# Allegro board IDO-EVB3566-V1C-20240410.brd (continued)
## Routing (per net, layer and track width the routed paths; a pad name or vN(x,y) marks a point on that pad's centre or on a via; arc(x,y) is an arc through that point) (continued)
PMIC_32KHZ_OUT_WIFI: length 48.7
  TOP w0.127: R74.1 84.74,32.7 v1(84.94,32.89) ; M1.180 48.53,47.61 49.33,46.81 49.33,39.09 v1(50.38,38.04)
  BOTTOM w0.127: v1(50.38,38.04) 50.62,37.8 64.43,37.8 64.79,37.45 70.08,37.45 73.36,34.16 81.81,34.16 83.08,32.89 v1(84.94,32.89)
PMIC_EXT_EN: length 83.2
  TOP w0.127: v1(72.37,44.4) 73.04,45.06 M1.167 ; v1(26.62,28.07) 25.9,28.07 25.5,27.67 25.5,25.68 v1(25.78,25.4) ; v1(13.38,21.89) 13.04,22.23 12.63,22.23 R11.1 ; v1(51.69,45.72) 51.33,45.36 51.33,34.48 50.83,33.99 v1(50.27,33.99)
  BOTTOM w0.127: v1(13.38,21.89) 16.7,21.89 18,23.18 18,24.89 18.25,25.15 25.53,25.15 v1(25.78,25.4) ; v1(51.69,45.72) 52.2,46.23 53.09,46.23 53.47,45.85 59.05,45.85 59.41,45.49 67.08,45.49 67.69,46.1 68.76,46.1 70.25,44.61 72.16,44.61 v1(72.37,44.4) ; v1(26.62,28.07) 26.79,28.07 27.87,29.15 28.26,29.15 28.68,28.73 30.24,28.73 30.97,29.46 31.99,29.46 31.99,29.46 32.13,29.46 35.47,32.81 48.58,32.81 49.26,33.49 49.38,33.49 49.88,33.99 v1(50.27,33.99)
PMIC_PWRON: length 89.2
  TOP w0.127: v1(67.89,45.47) 67.9,45.48 67.9,46.28 69.04,47.42 71.42,47.42 72.78,46.06 M1.168 ; v1(52,34.54) 51.79,34.76 51.79,45.15 v1(52.37,45.73) ; J46.2 9.3,32.1 8.89,32.51 v1(5.97,32.51)
  BOTTOM w0.127: v1(5.97,32.51) 6.54,31.94 D82.10 D82.1 7.94,31.94 8.09,31.78 10.13,31.78 11.14,30.77 12.61,30.77 13.69,31.85 16.23,31.85 16.41,32.03 21.27,32.03 22.35,30.95 26.96,30.95 27.71,31.7 30.43,31.7 30.66,31.93 31.77,31.93 34.51,34.67 46.3,34.67 47.06,35.43 51.11,35.43 v1(52,34.54) ; v1(67.89,45.47) 67.89,45.46 67.6,45.16 59.27,45.16 58.92,45.52 52.58,45.52 v1(52.37,45.73)
PMIC_VDC: length 8
  TOP w0.381: M1.169 72.6,47.06 71.91,47.76 v1(71.91,47.88)
  BOTTOM w0.127: D86.C 76.47,47.85 75.55,47.85 R20.2 R18.1 73.4,47.8 71.98,47.8 v1(71.91,47.88)
PWM0_M0_EDP: length 76.3
  TOP w0.127: v1(24.23,10.57) 24.07,10.41 J5.8 ; v1(64.01,17.44) 63.91,17.54 63.91,34.55 67.63,38.27 71.29,38.27 73.08,40.06 M1.162
  BOTTOM w0.127: v1(24.23,10.57) 24.48,10.82 34.88,10.82 35.39,10.3 38.95,10.3 45.15,16.51 46.03,16.51 47.17,17.65 63.8,17.65 v1(64.01,17.44)
PWM4_LVDS: length 42.4
  TOP w0.127: M1.155 73.07,33.06 72.54,32.54 72.54,31.93 71.47,30.86 69.52,30.86 69.09,30.43 69.09,29.45 68.31,28.67 66.01,28.67 65.25,27.91 65.25,18.29 65.49,18.05 65.49,17.48 66.03,16.94 66.03,15.91 66.52,15.42 66.52,15.06 66.53,15.05 66.53,14.71 66.52,14.7 66.52,13.79 66.72,13.59 68.23,13.59 68.38,13.74 68.92,13.74 69.2,13.46 70.62,13.46 71.38,12.71 71.5,12.63 71.62,12.58 71.76,12.55 71.9,12.55 72.03,12.57 74.47,12.57 74.78,12.88 75.41,12.88 75.7,12.59 75.7,11.02 74.8,10.12 74.8,7.5 75.05,7.25 J7.35
PWM5_MIPI: length 58.8
  TOP w0.127: v1(69.32,15.19) 69.32,15.72 68.89,16.15 68.89,16.7 68.78,16.81 68.78,18.8 67.97,19.61 66.5,19.61 66.29,19.81 66.29,27.36 66.59,27.66 68.8,27.66 69.47,28.32 72.25,28.32 72.51,28.06 M1.150 ; v1(49.73,14.13) 49.47,13.87 49.47,13.78 48.94,13.25 v1(48.94,12.87)
  BOTTOM w0.127: U6.4 44.67,4.76 45.11,4.32 R49.2 45.4,4.32 45.4,4.7 44.96,5.14 44.96,7.62 45.33,7.99 45.68,7.99 46.35,8.66 46.35,10.29 46.74,10.67 47.12,10.67 47.62,10.16 48.26,10.16 48.66,10.56 48.66,12.59 v1(48.94,12.87) ; v1(69.32,15.19) 69.14,15.37 68.53,15.37 67.61,16.28 66.78,16.28 65.95,15.45 63.18,15.45 62.76,15.87 51.26,15.87 49.73,14.35 v1(49.73,14.13)
PWM6_OUT: length 99.2
  TOP w0.127: J31.4 8,17.34 8,15.24 8.2,15.04 10.21,15.04 10.41,15.23 D45.2 D45.9 12.93,15.23 v1(13.47,14.7) ; v1(72.26,14.96) 72.54,15.24 72.54,21.92 71.68,22.79 71.68,24.56 73.18,26.06 M1.148
  BOTTOM w0.127: v1(13.47,14.7) 11.8,14.7 10.16,13.06 10.16,9.14 12.19,7.11 17.91,7.11 18.41,6.6 23.1,6.6 23.59,7.09 28.29,7.09 28.7,7.49 32.26,7.49 32.66,7.09 36.19,7.09 36.74,7.64 39.87,7.64 45.86,13.62 46.37,13.62 46.94,14.19 49.12,14.19 51.05,16.13 62.87,16.13 63.29,15.71 65.85,15.71 66.68,16.54 67.74,16.54 68.43,15.85 69.09,15.85 70,16.76 70.7,16.76 71.01,16.45 71.01,16.03 72.09,14.96 v1(72.26,14.96)
PWM7_IR: length 104.4
  TOP w0.127: v1(68.43,16.51) 68.43,16.51 68.5,16.59 68.5,18.54 67.69,19.35 66.37,19.35 66.04,19.68 66.04,27.47 66.48,27.91 68.63,27.91 69.29,28.57 71.25,28.57 71.73,29.06 M1.151 ; v1(13.46,15.37) 13.1,15.73 D45.10 D45.1 10.27,15.73 9.91,15.37 8.38,15.37 8.26,15.49 8.26,19.08 J31.2
  BOTTOM w0.127: v1(13.46,15.37) 13.93,14.91 13.93,14.47 13.21,13.74 11.42,13.74 10.41,12.74 10.41,9.25 11.49,8.17 17.87,8.17 19.18,6.86 23,6.86 23.48,7.34 28.19,7.34 28.59,7.75 32.37,7.75 32.77,7.34 36.09,7.34 36.76,8.02 39.9,8.02 45.76,13.88 46.27,13.88 46.84,14.45 49,14.45 50.93,16.38 62.97,16.38 63.39,15.96 64.73,15.96 64.77,16 65.79,16 66.57,16.79 68.16,16.79 68.43,16.52 v1(68.43,16.51)
RECOVERY_KEY: length 5.8
  BOTTOM w0.127: R25.2 62.36,64.84 C33.2 61.31,64.87 D5.1 60.2,65.63 61.16,66.6 SW4.3
RESETN: length 102.4
  TOP w0.127: v1(81.14,46.98) 80.97,46.81 80.31,46.81 80.09,47.03 80.09,47.61 79.82,47.88 79.44,47.88 78.94,47.38 77.99,47.38 77.74,47.13 77.74,46.19 77.46,45.92 v1(77.46,44.24) ; v1(50.64,34.92) 50.9,35.18 50.9,45.69 v1(50.96,45.75) ; v1(69.07,45.07) 69.1,45.07 69.54,45.51 M1.222 ; J46.3 9.28,30.85 8.41,31.73 v1(5.84,31.73)
  BOTTOM w0.127: v1(50.64,34.92) 50.52,35.05 47.15,35.05 46.44,34.34 34.72,34.34 31.98,31.6 30.79,31.6 30.56,31.37 27.85,31.37 27.1,30.62 21.58,30.62 20.5,31.7 16.59,31.7 16.26,31.37 13.72,31.37 12.43,30.09 11.1,30.09 9.75,31.44 D82.2 D82.9 6.13,31.44 v1(5.84,31.73) ; v1(50.96,45.75) 51.51,45.19 58.78,45.19 59.13,44.83 68.5,44.83 68.74,45.07 v1(69.07,45.07) 69.07,45.03 69.9,44.2 71.92,44.2 72.18,43.93 77.15,43.93 v1(77.46,44.24) ; v1(81.14,46.98) 81.14,48.4 R1231.2
RMII_CLK_: length 3.5
  BOTTOM w0.127: R1224.2 30.61,18.8 31.47,19.66 32.87,19.66 33.04,19.83 U11.15
RMII_CLK_CTL: length 2
  BOTTOM w0.127: U11.12 34.54,19.94 33.91,19.31 R1214.1
RMII_RST_: length 4.2
  BOTTOM w0.127: R1201.2 R1202.1 C384.2 30.86,23.11 31.12,22.86 U11.21
RN: length 50.7
  TOP w0.102: v1(42.79,21.45) 42.58,21.67 41.96,21.67 41.15,22.48 41.15,38.52 v1(40.94,38.74)
  BOTTOM w0.102: U23.1 30.23,37.64 29.8,37.21 29.08,37.21 28.99,37.11 28.99,36.83 28.73,36.58 27.96,36.58 27.71,36.83 26.42,36.83 26.31,36.73 26.31,35.31 26.34,35.28 26.4,35.28 26.56,35.43 26.56,35.7 26.99,36.13 D81.1 27.9,36.13 28.69,35.34 28.83,35.34 29.69,36.2 30.81,36.2 32.89,38.28 41.05,38.28 41.15,38.38 41.15,38.63 41.05,38.74 v1(40.94,38.74) ; U11.6 36.97,21.86 37.09,21.98 37.45,21.98 38.08,22.61 41.04,22.61 41.98,21.67 42.58,21.67 v1(42.79,21.45)
RP: length 50.7
  TOP w0.102: v1(42.79,22.13) 42.58,21.92 42.07,21.92 41.4,22.58 41.4,38.52 v1(41.61,38.74)
  BOTTOM w0.102: v1(41.61,38.74) 41.4,38.53 41.4,38.28 41.16,38.03 33,38.03 30.91,35.94 29.79,35.94 28.94,35.09 28.5,35.09 27.65,34.23 D81.3 27.11,34.23 26.56,34.79 26.56,34.92 26.45,35.03 26.23,35.03 26.06,35.2 26.06,36.83 26.31,37.08 27.81,37.08 28.07,36.83 28.63,36.83 28.73,36.94 28.73,37.11 28.61,37.24 28.33,37.24 27.69,37.89 U23.3 ; v1(42.79,22.13) 42.58,21.92 42.09,21.92 41.15,22.86 37.97,22.86 37.35,22.23 37.08,22.23 36.95,22.36 U11.5
RXD0: length 2.6
  BOTTOM w0.127: U11.9 36.04,20.03 36.93,19.15 37.18,19.15 R1206.1
RXD1: length 2.8
  BOTTOM w0.127: R1205.1 R1215.1 36.07,19.3 35.54,19.83 U11.10
RXDV: length 2.1
  BOTTOM w0.254: 37.47,20.57 37.18,20.85 U11.8
  BOTTOM w0.381: R1213.1 37.47,20.57
RXN: length 16.2
  TOP w0.102: J12.6 25.91,56.01 25.53,55.63 24.77,55.63 24.55,55.41 24.55,54.81 v1(24.75,54.62)
  BOTTOM w0.102: U23.16 30.23,48.39 29.36,49.25 29.03,49.25 28.96,49.33 28.96,49.64 27.77,50.82 27.77,50.97 28.16,51.36 28.16,51.72 27.73,52.15 27.37,52.15 26.98,51.76 26.83,51.76 26.55,52.05 26.55,52.19 26.94,52.59 26.94,52.94 26.51,53.38 26.15,53.38 25.76,52.98 25.61,52.98 24.59,54 24.59,54.46 v1(24.75,54.62)
RXP: length 16.2
  TOP w0.102: J12.3 22.85,56.01 23.24,55.63 24.03,55.63 24.3,55.36 24.3,54.84 v1(24.07,54.62)
  BOTTOM w0.102: U23.14 27.69,48.64 28.18,49.14 28.56,49.14 28.7,49.28 28.7,49.53 27.51,50.72 27.51,51.07 27.91,51.47 27.91,51.61 27.62,51.9 27.48,51.9 27.08,51.5 26.73,51.5 26.29,51.94 26.29,52.29 26.69,52.69 26.69,52.83 26.4,53.12 26.26,53.12 25.86,52.73 25.51,52.73 24.34,53.9 24.34,54.37 24.09,54.62 v1(24.07,54.62)
S0_RX: length 26.4
  TOP w0.127: v1(16.52,36.3) v1(17.46,36.3)
  BOTTOM w0.127: v1(17.46,36.3) 17.24,36.09 17.24,35.41 16.29,34.46 15.66,34.46 15.42,34.22 U22.13 ; v1(16.52,36.3) 16.52,37.55 13.33,40.74 9.41,40.74 9.25,40.89 R184.2 8.98,41 D43.1 D43.10 6.46,41 6.36,40.9 5.58,40.9 5.08,41.4 5.08,45.21 3.32,46.97 J42.2
S0_TX: length 27.8
  TOP w0.127: v1(16.42,35.6) 16.65,35.83 17.67,35.83 18.13,36.3 v1(18.13,36.32)
  BOTTOM w0.127: v1(16.42,35.6) 16.06,35.96 16.06,37.56 13.16,40.46 9.6,40.46 9.25,40.11 R183.2 8.37,40.5 D43.2 D43.9 6.49,40.5 6.34,40.65 4.82,40.65 4.57,40.89 4.57,43.94 3.54,44.97 J42.3 ; v1(18.13,36.32) 18.13,36.29 17.5,35.66 17.5,35.3 16.4,34.21 16.1,34.21 15.46,33.57 U22.14
S5_RX: length 13
  BOTTOM w0.127: R186.2 9.62,36.82 U22.8 8.52,36.82 8.38,36.96 8.38,39.06 7.94,39.51 D43.4 D43.7 5.98,39.51 5.08,38.61 5.08,38.59 J43.2
S5_TX: length 14.5
  BOTTOM w0.127: J43.3 4.22,35.73 4.22,37.11 6.11,39.01 D43.6 D43.5 7.98,39.01 8.13,38.86 8.13,36.56 8.52,36.17 U22.7 9.84,36.17 R185.2
S7_RX: length 28
  BOTTOM w0.127: U21.13 16.05,27.23 R174.2 17.13,26.16 17.2,26.16 17.75,25.61 17.75,23.33 16.76,22.35 5.46,22.35 1.91,18.8 1.91,15.44 2.38,14.97 J40.2
S7_TX: length 24.9
  BOTTOM w0.127: J40.3 1.65,14.11 1.65,19 3,20.35 5.26,22.61 12.26,22.61 R173.2 13.55,23.89 13.55,24.68 13.08,25.15 13.08,26.29 13.38,26.58 U21.14
S9_RX: length 14.9
  BOTTOM w0.127: R176.2 11.18,25.27 11.02,25.43 11.02,28.47 9.66,29.83 U21.8 8.52,29.83 8,29.31 6.35,29.31 4.57,27.54 4.57,27.18 3.03,25.64 J41.2
S9_TX: length 16.7
  BOTTOM w0.127: J41.3 5.16,26 5.16,27.76 6.35,28.96 8.39,28.96 8.61,29.18 U21.7 9.8,29.18 10.72,28.27 10.72,24.82 10.69,24.79 10.69,23.88 R175.2
SARADC_VIN0/RECOVERY: length 32.3
  TOP w0.127: v1(67.43,50.42) 68.02,50.42 68.93,49.51 68.93,47.85 67.43,46.35 67.43,41.92 67.9,41.44 72.3,41.44 72.92,42.06 M1.164
  BOTTOM w0.127: R25.1 62.38,61.58 64.99,58.97 64.99,56.57 66.48,55.09 66.48,51.37 v1(67.43,50.42)
SARADC_VIN1: length 43.3
  TOP w0.152: M1.231 30.37,39.51 30.43,39.57 31.93,39.57 32.26,39.24 32.26,36.64 31.29,35.67 31.29,31.18 v1(31.24,31.13) ; v1(5.84,30.14) 8.89,30.14 9.43,29.6 J46.4
  BOTTOM w0.152: v1(31.24,31.13) 31.11,31 27.97,31 27.19,30.23 21.33,30.23 20.46,31.1 16.6,31.1 16.5,31 13.85,31 12.51,29.67 11.03,29.67 9.95,30.75 8.26,30.75 7.95,30.44 D82.4 D82.7 6.14,30.44 v1(5.84,30.14)
SARADC_VIN2: length 89
  TOP w0.152: M1.165 71.87,43.06 70.68,44.25 68.99,44.25 v1(68.78,44.46) ; v1(5.84,29.47) 8.25,29.47 9.37,28.35 J46.5 ; v1(48.34,46.02) 47.93,45.04 47.93,34.72 v1(47.37,34.16)
  BOTTOM w0.152: v1(48.34,46.02) 49.99,46.02 51.17,44.84 58.64,44.84 58.99,44.49 68.62,44.49 68.65,44.46 v1(68.78,44.46) ; v1(47.37,34.16) 47.21,34 34.86,34 31.51,30.65 28.11,30.65 27.19,29.72 21.34,29.72 20.35,30.7 18,30.7 17.45,30.15 16.59,30.15 16.09,30.65 14,30.65 12.56,29.21 10.99,29.21 9.93,30.26 8.28,30.26 7.95,29.94 D82.5 D82.6 6.31,29.94 v1(5.84,29.47)
SDMMC0_CLK_: length 13.4
  BOTTOM w0.127: R160.2 36.58,49.59 C155.2 36.61,49.6 37.03,49.17 39.4,49.17 40.69,50.47 40.69,51.82 40.31,52.2 40.06,52.2 D34.1 D34.10 39.98,53.64 40.06,53.64 40.07,53.64 40.45,53.64 40.46,53.64 41.07,53.64 41.07,53.64 41.22,53.64 41.96,54.38 J21.5
SDMMC0_CLK_SD: length 2.1
  TOP w0.127: M1.37 36.03,50.89 35.69,50.55 v1(35.69,50.32)
  BOTTOM w0.127: v1(35.69,50.32) R160.1
SDMMC0_CMD_SD: length 15.8
  TOP w0.127: M1.33 40.03,50.67 40.16,50.55 41.78,50.55 41.91,50.42 41.91,49.91 41.78,49.78 v1(41.61,49.78)
  BOTTOM w0.127: J21.3 44.16,54.4 44.71,53.84 D33.7 D33.4 44.71,51.73 44.82,51.62 45.35,51.62 45.46,51.51 45.46,51.35 45.35,51.24 44.82,51.24 44.71,51.12 44.71,50.86 44.82,50.75 45.18,50.75 45.29,50.63 45.29,50.48 45.18,50.36 44.82,50.36 44.71,50.25 44.71,49.92 44.42,49.63 43.2,49.63 43.08,49.76 43.08,50.06 42.95,50.19 42.7,50.19 42.57,50.06 42.57,49.76 42.44,49.63 41.77,49.63 v1(41.61,49.78)
SDMMC0_D0_SD: length 12.9
  TOP w0.127: M1.35 v1(38.03,50.42)
  BOTTOM w0.127: J21.7 39.76,54.51 39.23,53.99 D34.9 D34.2 39.23,52.13 39.5,51.87 40.21,51.87 40.36,51.71 40.36,50.55 39.98,50.16 39.25,50.16 39.12,50.29 39.12,51.74 38.99,51.87 38.74,51.87 38.61,51.74 38.61,50.29 38.49,50.16 38.29,50.16 v1(38.03,50.42)
SDMMC0_D1_SD: length 13.4
  TOP w0.127: M1.32 41.03,52.17 40.91,52.3 40.21,52.3 40.08,52.43 40.08,52.68 39.95,52.81 39.7,52.81 39.57,52.68 39.57,52.43 39.45,52.3 39.19,52.3 39.06,52.43 39.06,52.68 38.94,52.81 38.68,52.81 38.56,52.68 38.56,52.43 38.43,52.3 38.18,52.3 38.05,52.43 38.05,52.68 37.92,52.81 37.67,52.81 37.54,52.68 37.54,52.43 37.41,52.3 37.21,52.3 v1(37.01,52.5)
  BOTTOM w0.127: J21.8 38.65,54.83 38.23,54.41 38.23,53.4 D34.7 D34.4 38.24,51.9 37.5,51.17 37.32,51.17 37.01,51.49 v1(37.01,52.5)
SDMMC0_D2_SD: length 17.7
  TOP w0.127: M1.36 37.03,50.72 37.34,50.42 37.34,48.7 v1(37.34,48.7)
  BOTTOM w0.127: v1(37.34,48.7) 42.06,48.7 42.34,48.98 44.66,48.98 46.21,50.53 D33.1 D33.10 46.21,54.09 46.35,54.23 J21.1
SDMMC0_D3_SD: length 13.8
  TOP w0.127: M1.34 39.03,51.23 40.11,50.15 40.61,50.15 40.74,50.02 v1(40.74,49.65)
  BOTTOM w0.127: v1(40.74,49.65) 40.74,49.63 41.07,49.3 44.48,49.3 45.71,50.54 D33.2 D33.9 45.71,54.34 45.25,54.8 J21.2
SDMMC0_DET_L_SD: length 57.7
  TOP w0.127: v1(36.7,50.32) 36.7,49.99 36.88,49.82 36.88,48.9 36.87,48.89 36.87,48.51 36.88,48.5 36.88,44.38 v1(36.84,44.34) ; v1(66.87,45.96) 66.87,41.71 67.52,41.06 M1.163
  BOTTOM w0.127: v1(36.84,44.34) 37.28,44.78 38.82,44.78 39.69,45.65 41.33,45.65 41.7,46.02 43.12,46.02 43.41,45.73 46.03,45.73 46.91,46.61 53.06,46.61 53.57,46.1 59.16,46.1 59.51,45.75 66.71,45.75 66.87,45.91 v1(66.87,45.96) ; J21.9 37.55,54.34 37.74,54.16 D34.6 D34.5 37.17,53.09 36.4,53.09 36.25,52.93 36.25,50.77 v1(36.7,50.32) 36.7,50.29 37.34,49.66 R344.2
SDMMC1_CLK_WIFI: length 66.2
  TOP w0.127: M1.49 24.1,50.06 24.5,49.67 24.5,49.25 25.27,48.47 25.27,47.49 25.92,46.84 27.03,46.84 27.71,46.15 27.71,44.18 28.4,43.48 28.4,41.8 28.88,41.33 32.69,41.33 33.67,40.34 v1(34.64,40.34) ; R67.1 v1(78.29,41.15)
  BOTTOM w0.127: v1(34.64,40.34) 34.64,40.64 36.56,42.57 37.55,42.57 38.24,43.25 39.51,43.25 40.38,44.12 41.63,44.12 41.94,43.81 48.81,43.81 49.81,42.81 52.08,42.81 52.88,42.02 56.01,42.02 56.63,41.4 65.05,41.4 65.78,42.13 67.71,42.13 68.02,42.44 68.76,42.44 69.13,42.08 74.99,42.08 75.92,41.15 v1(78.29,41.15)
SDMMC1_CMD_WIFI: length 70.2
  TOP w0.127: M1.54 24.15,45.06 24.52,44.69 24.52,43.91 25.03,43.4 25.03,41.2 25.66,40.56 27.46,40.56 28.02,40.01 28.02,38.64 29.07,37.59 30.08,37.59 30.42,37.94 31.27,37.94 31.29,37.91 v1(31.52,37.91) ; v1(79.88,41.89) 79.88,42.04 79.19,42.73 R66.2 79.55,42.75 79.76,42.55 79.88,42.55 80.51,41.92 U10.16
  BOTTOM w0.127: v1(79.88,41.89) 79.63,42.14 75.88,42.14 75.44,42.59 69.34,42.59 68.95,42.98 67.83,42.98 67.5,42.64 65.57,42.64 65.26,42.33 56.42,42.33 56.22,42.53 53.7,42.53 52.91,43.32 50.02,43.32 49.02,44.32 42.15,44.32 41.84,44.63 40.17,44.63 39.3,43.76 38,43.76 37.33,43.1 36.37,43.1 32.64,39.37 32.64,38.73 31.82,37.91 v1(31.52,37.91)
SDMMC1_D0_WIFI: length 69.7
  TOP w0.127: v1(33.27,39.16) 33.27,39.75 32.32,40.71 28.49,40.71 27.64,41.56 27.64,43.23 27.28,43.59 26.14,43.59 25.29,44.44 25.29,45.4 25.02,45.67 25.02,46.66 24.51,47.17 24.51,47.62 24.07,48.06 M1.51 ; U10.18 80.45,40.12 80.26,40.31 80.13,40.31 v1(79.88,40.56) 79.66,40.33 79.66,40.16 79.19,39.69 R65.2
  BOTTOM w0.127: v1(33.27,39.16) 33.27,39.33 33.57,39.62 34.93,39.62 35.48,40.17 35.48,40.77 36.77,42.06 37.76,42.06 38.45,42.75 39.72,42.75 40.59,43.61 41.42,43.61 41.8,43.24 48.67,43.24 50.4,41.51 55.8,41.51 56.42,40.89 65.48,40.89 66.1,41.51 74.63,41.51 75.88,40.26 79.59,40.26 v1(79.88,40.56)
SDMMC1_D1_WIFI: length 68.8
  TOP w0.127: U10.19 80.21,39.22 79.89,39.54 v1(79.89,39.73) ; M1.50 23.96,49.06 24.77,48.26 24.77,47.28 25.54,46.5 25.54,44.54 26.24,43.84 27.38,43.84 28.02,43.21 28.02,41.58 28.64,40.96 32.42,40.96 33.95,39.43 v1(33.95,39.16)
  BOTTOM w0.127: v1(33.95,39.16) 34.83,39.16 35.74,40.07 35.74,40.66 36.88,41.8 37.87,41.8 38.55,42.49 39.83,42.49 40.69,43.36 41.32,43.36 41.69,42.99 48.56,42.99 50.29,41.26 55.7,41.26 56.32,40.64 65.58,40.64 66.2,41.26 74.52,41.26 76.05,39.73 v1(79.89,39.73)
SDMMC1_D2_WIFI: length 68.5
  TOP w0.127: v1(31.01,37.47) 30.61,37.47 30.48,37.34 28.96,37.34 27.83,38.47 25.85,38.47 25.39,38.93 25.39,40.48 24.78,41.09 24.78,43.29 24.01,44.06 M1.55 ; v1(79.51,43.44) 79.88,43.81 80.24,43.81 80.34,43.72 U10.14
  BOTTOM w0.127: v1(79.51,43.44) 79.15,43.09 69.55,43.09 69.16,43.48 67.62,43.48 67.29,43.15 65.36,43.15 65.05,42.84 56.63,42.84 56.44,43.03 53.91,43.03 53.12,43.83 50.23,43.83 49.23,44.83 42.36,44.83 42.05,45.14 39.96,45.14 39.09,44.27 37.79,44.27 37.12,43.6 35.98,43.6 34.03,41.65 33.61,41.65 33.27,41.31 33.27,40.39 32.38,39.5 32.38,38.99 31.77,38.38 31.28,38.38 31.01,38.1 v1(31.01,37.47)
SDMMC1_D3_WIFI: length 69.4
  TOP w0.127: U10.15 80.56,42.82 80.39,42.99 v1(80.01,42.99) ; v1(33.74,41.12) 33.11,41.75 30.89,41.75 30.73,41.91 30.73,42.34 30.76,42.37 31,42.37 31.12,42.48 31.12,42.64 31,42.75 30.73,42.75 30.71,42.78 30.71,43.27 30.47,43.51 28.91,43.51 27.99,44.42 27.99,47.33 27.97,47.36 27.67,47.36 27.56,47.47 27.56,47.63 27.67,47.74 28.02,47.74 28.13,47.85 28.13,48.01 28.02,48.12 27.67,48.12 27.56,48.23 27.56,48.39 27.67,48.5 28.02,48.5 28.13,48.61 28.13,48.95 26.9,50.19 26.01,50.19 25.03,51.17 M1.48
  BOTTOM w0.127: v1(33.74,41.12) 33.86,41.12 36.09,43.35 37.23,43.35 37.89,44.02 39.19,44.02 40.06,44.88 41.95,44.88 42.25,44.58 49.13,44.58 50.13,43.58 53.01,43.58 53.81,42.78 56.33,42.78 56.52,42.59 65.15,42.59 65.46,42.9 67.39,42.9 67.73,43.23 69.05,43.23 69.44,42.84 79.86,42.84 v1(80.01,42.99)
SPI3_CLK_M1_OUT: length 65.8
  TOP w0.127: M1.206 52.48,14.84 51.18,16.14 v1(48.48,16.14) ; J31.1 10.43,18.91 D44.1 D44.10 13.06,18.91 v1(13.34,19.18)
  BOTTOM w0.127: v1(13.34,19.18) 13.06,18.91 12.68,18.91 12.45,18.67 12.45,16.38 12.83,16 13.55,16 14.44,15.12 14.44,14.26 13.42,13.23 11.63,13.23 10.92,12.53 10.92,9.46 11.62,8.76 20.11,8.76 20.76,9.41 23.17,9.41 23.46,9.12 27.28,9.12 28.22,10.06 34.56,10.06 35.08,9.54 39.26,9.54 45.12,15.4 45.64,15.4 47,16.76 47.85,16.76 v1(48.48,16.14)
SPI3_CS0_M1_OUT: length 31.7
  TOP w0.127: v1(13.44,16.98) 13.2,16.98 13.13,16.91 D44.6 D44.5 10.68,16.91 v1(10.29,16.51) ; v1(35.79,15.77) 35.73,15.77 35.58,15.62 M1.201
  BOTTOM w0.127: v1(10.29,16.51) 10.29,15.34 J31.7 ; v1(35.79,15.77) 35.58,15.77 35.38,15.57 35.08,15.57 35.08,15.57 34.35,15.57 33.06,16.86 27.63,16.86 26.8,17.7 21.7,17.7 20.98,18.41 18.54,18.41 17.02,16.89 15.38,16.89 15.3,16.98 v1(13.44,16.98)
SPI3_MISO_M1_OUT: length 34
  TOP w0.127: M1.202 38.58,16.03 v1(37.86,16.75) ; v1(13.42,17.65) 13.19,17.65 12.94,17.41 D44.7 D44.4 10.36,17.41 J31.5
  BOTTOM w0.127: v1(37.86,16.75) 37.85,16.75 37.32,16.23 35.38,16.23 34.98,15.82 34.46,15.82 33.16,17.12 27.73,17.12 26.9,17.95 21.8,17.95 21.08,18.67 18.42,18.67 17.12,17.37 15.57,17.37 15.29,17.65 v1(13.42,17.65)
SPI3_MOSI_M1_OUT: length 55.3
  TOP w0.127: v1(13.38,18.5) 13.28,18.41 D44.9 D44.2 9.36,18.41 J31.3 ; M1.204 44.58,15.28 v1(45.21,15.91)
  BOTTOM w0.127: v1(13.38,18.5) 12.95,18.08 12.95,16.64 13.08,16.51 13.76,16.51 14.65,15.62 14.95,15.33 14.95,14.05 12.76,11.85 12.13,11.85 11.43,11.15 11.43,9.91 12.06,9.27 18.29,9.27 19.44,10.41 23.27,10.41 23.68,10 26.26,10 26.57,10.31 27.75,10.31 28.01,10.57 34.77,10.57 35.29,10.05 39.05,10.05 42.57,13.56 44.91,15.91 v1(45.21,15.91)
SYS_LED_H: length 86.2
  TOP w0.127: v1(24.77,29) 24.77,29.72 24.42,30.06 M1.69 ; v1(61.1,34.53) 61.09,34.53 61.09,34.54 59.94,35.69 59.94,50.16 60.35,50.57 62.59,50.57 v1(62.74,50.42) ; v1(67.44,65.32) 65.23,63.12 v1(61.85,63.12)
  BOTTOM w0.127: v1(61.85,63.12) 61.85,61.57 64.61,58.81 64.61,54.83 64.14,54.36 64.14,52.32 62.74,50.93 v1(62.74,50.42) ; R1227.1 70.62,62.16 R415.2 67.46,65.32 v1(67.44,65.32) ; v1(24.77,29) 26.95,29 28.26,30.3 31.76,30.3 35.02,33.57 47.44,33.57 48.49,34.62 50.29,34.62 50.45,34.46 50.88,34.46 51.44,33.91 60.45,33.91 61.09,34.54 61.09,34.53 v1(61.1,34.53)
TN: length 56.9
  TOP w0.102: v1(42.4,37.97) 42.61,37.76 42.61,36.75 42.04,36.17 42.04,23.62 42.29,23.37 42.54,23.37 v1(42.75,23.16)
  BOTTOM w0.102: v1(42.75,23.16) 42.54,23.37 37.72,23.37 37.33,22.98 37.08,22.98 36.95,22.86 U11.4 ; U23.6 23.88,37.85 23.11,37.08 22.86,37.08 22.73,36.96 22.73,36.68 22.83,36.58 23.5,36.58 24.08,37.16 25.05,37.16 25.65,36.55 25.65,35.71 25.27,35.33 25.27,34.8 24.7,34.23 D81.4 24.32,34.23 23.5,35.05 22.97,35.05 22.73,34.82 22.73,33.85 22.83,33.75 28.21,33.75 29.9,35.43 31.14,35.43 33.22,37.52 42.48,37.52 42.58,37.62 42.58,37.79 v1(42.4,37.97)
TP: length 56.8
  TOP w0.102: v1(42.75,23.83) 42.54,23.62 42.39,23.62 42.29,23.72 42.29,36.07 42.86,36.64 42.86,37.76 v1(43.07,37.97)
  BOTTOM w0.102: U23.8 21.34,37.48 21.74,37.08 22.23,37.08 22.48,36.83 22.48,36.57 22.73,36.32 23.6,36.32 24.18,36.9 24.94,36.9 25.4,36.45 25.4,35.81 25.34,35.76 25.2,35.76 24.83,36.13 D81.6 24.32,36.13 23.5,35.31 22.86,35.31 22.48,34.92 22.48,33.75 22.73,33.5 28.32,33.5 30,35.18 31.24,35.18 33.32,37.26 42.58,37.26 42.83,37.51 42.83,37.85 42.96,37.97 v1(43.07,37.97) ; v1(42.75,23.83) 42.54,23.62 37.61,23.62 37.23,23.23 37.09,23.23 36.97,23.36 U11.3
TP1_INT: length 35.9
  TOP w0.127: v1(64.26,2) 63.2,3.06 63.2,4.88 63.88,5.56 J9.3 63.88,7.36 64.52,8 v1(65.02,8) ; v1(48.9,4.06) 50.01,5.18 51.66,5.18 52.58,6.1 J8.5
  BOTTOM w0.127: R44.2 67.94,10.46 D18.9 D18.2 67.94,7.74 67.55,7.35 66.1,7.35 65.45,8 v1(65.02,8) ; v1(64.26,2) 63.57,2.69 62.58,2.69 62.16,2.27 49.93,2.27 48.9,3.3 v1(48.9,4.06)
TP1_RST: length 32.2
  TOP w0.127: v1(65.53,7.26) 65.3,7.49 64.52,7.49 64.38,7.35 J9.2 64.38,5.58 63.83,5.03 v1(63.83,4.14) ; J8.4 53.08,6.1 51.9,4.92 50.11,4.92 49.67,4.48 v1(49.67,4.06)
  BOTTOM w0.127: v1(63.83,4.14) 62.64,2.95 62.47,2.95 62.07,2.54 50.01,2.54 49.67,2.89 v1(49.67,4.06) ; R43.2 68.44,9.95 D18.10 D18.1 68.44,7.88 67.66,7.1 65.69,7.1 v1(65.53,7.26)
TP1_SCL: length 37.7
  TOP w0.127: v1(63.58,2.02) 62.79,2.81 62.79,5.03 63.38,5.62 J9.4 63.38,7.88 64.18,8.68 v1(65.02,8.68) ; J8.6 52.08,6.1 51.41,5.43 49.6,5.43 v1(49.39,5.22)
  BOTTOM w0.127: v1(65.02,8.68) 65.13,8.68 66.06,7.75 66.46,7.75 66.94,8.22 D18.4 D18.7 66.94,10.48 R42.1 67.56,11.11 67.56,12.5 R41.2 ; v1(63.58,2.02) 63.16,2.44 62.68,2.44 62.26,2.01 49.65,2.01 48.34,3.32 48.34,4.17 v1(49.39,5.22)
TP1_SDA: length 38.1
  TOP w0.127: v1(62.88,1.97) 62.43,2.42 62.43,5.41 62.88,5.85 J9.5 62.88,7.89 64.14,9.14 v1(65.53,9.14) ; J8.7 51.58,6.09 51.18,5.68 49.12,5.68 v1(48.64,5.21)
  BOTTOM w0.127: v1(62.88,1.97) 62.67,1.76 49.55,1.76 48.09,3.22 48.09,4.65 v1(48.64,5.21) ; R39.2 65.41,12 65.41,11.23 R40.1 66.44,10.2 D18.6 D18.5 66.44,8.16 66.31,8.04 66.13,8.04 66,8.16 66,9.02 65.88,9.14 v1(65.53,9.14)
TXN: length 10.9
  TOP w0.102: J12.2 21.83,56.12 21.46,55.75 21.46,55.6 21.69,55.37 21.69,54.93 v1(21.9,54.72)
  BOTTOM w0.102: U23.11 23.88,48.39 22.61,49.66 22.61,52.55 21.74,53.42 21.74,54.56 v1(21.9,54.72)
TXP: length 10.9
  TOP w0.102: v1(21.23,54.72) 21.44,54.93 21.44,55.27 21.2,55.5 21.2,55.76 20.81,56.15 J12.1
  BOTTOM w0.102: U23.9 21.34,48.64 22.35,49.66 22.35,52.45 21.49,53.31 21.49,54.54 21.31,54.72 v1(21.23,54.72)
UART0_RX: length 80.8
  TOP w0.127: v1(71.66,32.87) 71.76,32.97 71.76,34.19 72.63,35.06 M1.157
  BOTTOM w0.127: v1(71.66,32.87) 71.66,33.3 69.18,35.77 62.91,35.77 62.48,36.2 60.96,36.2 59.94,35.18 53.34,35.18 51.99,36.53 46.61,36.53 45.86,35.77 34.06,35.77 31.33,33.04 30.17,33.04 29.92,32.79 25.6,32.79 25.21,32.4 22.44,32.4 19.52,35.33 19.52,40.81 16.89,43.43 10.16,43.43 9.78,43.05 9.78,41.65 R184.1 R189.1
UART0_TX: length 90
  TOP w0.127: v1(10.74,39.62) 10.74,42.6 v1(10.79,42.65) ; v1(72.08,32.32) 72.08,32.45 72.26,32.64 72.26,33.53 72.8,34.06 M1.156
  BOTTOM w0.127: U22.11 15.68,35.52 15.81,35.65 15.81,37.18 12.85,40.13 10.28,40.13 10.15,40.01 R183.1 v1(10.74,39.62) ; v1(72.08,32.32) 71.94,32.32 71.86,32.4 71.46,32.4 71.19,32.68 71.19,33.4 69.08,35.52 62.8,35.52 62.38,35.94 61.09,35.94 60.07,34.92 53.17,34.92 51.82,36.28 46.72,36.28 45.96,35.52 34.17,35.52 31.44,32.79 30.28,32.79 30.03,32.54 25.7,32.54 25.32,32.15 22.34,32.15 19.21,35.27 19.21,40.76 16.91,43.05 11.2,43.05 v1(10.79,42.65)
UART1_CTSN_M0_WIFI: length 80.6
  TOP w0.127: U10.41 93.04,42.82 93.17,42.7 93.17,41.55 93.5,41.22 93.98,41.22 v1(94.63,40.58) 95.33,41.28 R69.1 ; M1.39 34.03,50.93 35.2,49.76 36.27,49.76 36.63,49.4 36.63,49.01 36.62,49 36.62,48.4 36.63,48.39 36.63,44.79 36.2,44.36 v1(35.94,44.36)
  BOTTOM w0.127: v1(94.63,40.58) 92.66,38.61 86,38.61 79.75,44.86 78.95,44.86 78.89,44.8 72.63,44.8 72.57,44.86 70.35,44.86 68.79,46.42 66.52,46.42 66.09,46 59.62,46 59.2,46.42 53.61,46.42 53.17,46.86 46.81,46.86 45.92,45.98 43.51,45.98 43.22,46.27 41.59,46.27 41.22,45.9 39.58,45.9 38.71,45.03 36.65,45.03 35.98,44.36 v1(35.94,44.36)
UART1_RTSN_M0_WIFI: length 75.6
  TOP w0.127: U10.44 93.06,45.52 94.48,44.1 v1(94.48,42.55) ; v1(34.92,46.66) 34.54,47.04 34.54,50.06 34.03,50.57 33.5,50.57 33.03,51.04 M1.40
  BOTTOM w0.127: v1(34.92,46.66) 36.26,46.66 37.13,45.79 38.4,45.79 39.27,46.66 40.91,46.66 41.28,47.03 43.54,47.03 43.83,46.74 45.46,46.74 46.34,47.62 68.67,47.62 70.67,45.62 72.88,45.62 72.95,45.56 78.39,45.56 78.43,45.59 78.6,45.59 78.64,45.62 80.53,45.62 86.27,39.88 90.42,39.88 93.1,42.55 v1(94.48,42.55)
UART1_RX_M0_WIFI: length 86.3
  TOP w0.127: U10.42 92.91,43.72 93.52,43.1 93.52,42.27 93.75,42.04 v1(93.75,41.78) ; v1(32.78,42.22) 32.12,42.22 30.55,43.79 29.11,43.79 28.24,44.65 28.24,47.4 28.3,47.45 28.3,47.65 28.39,47.75 28.39,48.12 28.39,48.12 28.39,48.51 28.39,48.51 28.39,49.21 27.13,50.47 26.39,50.47 26.03,50.83 M1.47
  BOTTOM w0.127: v1(93.75,41.78) 90.98,39.01 86.06,39.01 79.95,45.12 78.85,45.12 78.81,45.09 78.64,45.09 78.6,45.05 72.74,45.05 72.67,45.12 70.46,45.12 68.9,46.68 68.69,46.68 66.41,46.68 65.99,46.25 59.72,46.25 59.3,46.68 53.71,46.68 53.27,47.12 46.65,47.12 45.77,46.23 43.62,46.23 43.33,46.52 41.49,46.52 41.12,46.15 39.48,46.15 38.61,45.29 33.48,45.29 32.78,44.59 v1(32.78,42.22)
UART1_TX_M0_WIFI: length 86.8
  TOP w0.127: M1.46 27.03,50.97 28.64,49.36 28.64,48.4 28.64,48.4 28.64,48.22 28.64,48.22 28.64,47.64 28.55,47.55 28.55,47.34 28.5,47.29 28.5,44.76 29.21,44.04 30.65,44.04 31.14,43.56 31.44,43.56 v1(32.26,42.74) ; U10.43 93.02,44.62 93.88,43.76 93.88,42.48 v1(94.49,41.88)
  BOTTOM w0.127: v1(94.49,41.88) 94.11,42.25 93.48,42.25 90.6,39.37 86.23,39.37 80.23,45.37 78.74,45.37 78.71,45.34 78.53,45.34 78.5,45.31 72.84,45.31 72.78,45.37 70.56,45.37 69,46.93 68.58,46.93 66.3,46.93 65.88,46.51 59.83,46.51 59.41,46.93 53.82,46.93 53.38,47.37 46.55,47.37 45.66,46.49 43.72,46.49 43.43,46.78 41.38,46.78 41.01,46.41 39.37,46.41 38.5,45.54 33.09,45.54 32.26,44.7 v1(32.26,42.74)
UART2_RX_M0_DEBUG: length 84
  TOP w0.127: R161.1 11.43,50.48 11.43,42.67 v1(11.56,42.55) ; M1.153 72.71,31.06 v1(72.39,30.74)
  BOTTOM w0.127: v1(72.39,30.74) 71.72,30.74 70.61,31.85 70.61,33.62 68.97,35.26 62.7,35.26 62.27,35.69 61.21,35.69 60.2,34.67 53.06,34.67 51.71,36.02 46.83,36.02 46.07,35.26 34.27,35.26 31.52,32.51 30.36,32.51 30.13,32.28 25.81,32.28 25.42,31.9 22.23,31.9 18.96,35.17 18.96,40.65 16.81,42.8 11.68,42.8 11.56,42.67 v1(11.56,42.55)
UART2_TX_M0_DEBUG: length 80.1
  TOP w0.127: v1(10.24,42.04) 10.16,41.95 R162.1 ; M1.152 v1(72.39,30.06)
  BOTTOM w0.127: v1(10.24,42.04) 10.29,42.08 11.85,42.08 12.32,42.55 16.7,42.55 18.7,40.54 18.7,35.06 22.18,31.59 25.47,31.59 25.91,32.03 30.25,32.03 30.48,32.26 31.63,32.26 34.38,35.01 46.17,35.01 46.93,35.77 51.61,35.77 52.96,34.42 60.33,34.42 61.34,35.43 62.17,35.43 62.59,35.01 68.87,35.01 70.33,33.54 70.33,31.78 70.36,31.75 70.36,31.75 71.62,30.48 71.62,30.48 72.05,30.06 v1(72.39,30.06)
UART5_RX_M1: length 46
  TOP w0.127: v1(9.34,37.47) 9.17,37.63 5.5,37.63 4.49,36.62 4.49,21.25 v1(4.78,20.95) ; M1.80 23.1,19.06 v1(22.73,19.43)
  BOTTOM w0.127: v1(4.78,20.95) 4.78,20.99 5.89,22.1 12.51,22.1 13.18,21.42 13.85,21.42 15.8,19.47 22.69,19.47 v1(22.73,19.43) ; R186.1 12.31,38.75 R190.1 9.34,37.53 v1(9.34,37.47)
UART5_TX_M1: length 48.3
  TOP w0.127: v1(5.46,20.94) 4.74,21.66 4.74,36.51 5.61,37.38 8.77,37.38 10.08,36.07 v1(10.54,36.07) ; M1.81 23.09,18.06 v1(22.73,18.42)
  BOTTOM w0.127: v1(22.73,18.42) 22.61,18.42 21.8,19.22 15.7,19.22 13.75,21.17 13.08,21.17 12.4,21.84 6.37,21.84 v1(5.46,20.94) ; U22.10 14.22,36.17 12.8,37.59 12.8,37.59 12.65,37.74 R185.1 10.87,36.31 10.78,36.31 v1(10.54,36.07)
UART7_RX_M2: length 10.6
  TOP w0.127: M1.73 24.03,26.06 v1(24.51,26.54)
  BOTTOM w0.127: v1(24.51,26.54) 23.62,25.65 18.06,25.65 17.39,26.32 R174.1 R178.1
UART7_TX_M2: length 24.5
  TOP w0.127: v1(21.59,26.56) 22.08,27.05 22.08,30.8 22.44,31.16 22.44,36.18 23.32,37.06 M1.62
  BOTTOM w0.127: v1(21.59,26.56) 21.55,26.56 20.29,27.81 18.41,27.81 17.69,28.53 U21.11 14.32,28.53 12.83,27.04 12.83,24.87 13.06,24.64 R173.1
UART9_RX_M2: length 19.8
  TOP w0.127: v1(24.77,27.81) 24.52,28.06 M1.71
  BOTTOM w0.127: v1(24.77,27.81) 22.4,27.81 21.77,28.45 18.63,28.45 18.03,29.04 17.64,29.04 R177.1 16.88,29.8 16.33,29.8 15.83,30.3 14.14,30.3 13.72,29.88 13.72,29.08 12.08,27.45 R176.1
UART9_TX_M2: length 25.5
  TOP w0.127: M1.61 23.46,38.06 22.84,37.45 22.84,36.94 22.18,36.28 22.18,31.26 21.83,30.91 21.83,28.15 v1(21.62,27.94)
  BOTTOM w0.127: v1(21.62,27.94) 21.36,28.19 18.52,28.19 17.93,28.79 16.04,28.79 15.65,29.18 U21.10 14.32,29.18 12.57,27.44 12.57,23.93 R175.1
USB3_HOST1_DM: length 6.6
  TOP w0.114: v1(57.01,56.03) 57.19,55.85 57.53,55.85 57.78,55.59 57.78,54.65 56.65,53.52 56.65,51.94 M1.16
  BOTTOM w0.114: R124.1 56.33,55.92 56.44,55.81 56.79,55.81 v1(57.01,56.03)
USB3_HOST1_DM_2: length 19.3
  TOP w0.114: v1(43.65,60.32) 43.43,60.1 43.43,59.69 44.31,58.82 J16.2
  BOTTOM w0.114: v1(43.65,60.32) 43.38,60.05 43.38,59.35 44.19,58.55 53.12,58.55 53.59,58.08 53.59,56.06 53.85,55.81 54.11,55.81 54.23,55.92 D28.2 54.8,55.72 55.34,55.72 55.43,55.81 R124.2
USB3_HOST1_DP: length 6.7
  TOP w0.114: M1.17 56.41,51.94 56.41,52.36 56.3,52.48 56.22,52.48 56.11,52.59 56.11,52.82 56.22,52.93 56.3,52.93 56.41,53.05 56.41,53.62 57.54,54.75 57.54,55.49 57.43,55.61 57.2,55.61 57.01,55.42 v1(57.01,55.35)
  BOTTOM w0.114: R126.1 56.33,55.45 56.44,55.57 56.79,55.57 v1(57.01,55.35)
USB3_HOST1_DP_2: length 19.3
  TOP w0.114: v1(42.97,60.32) 43.19,60.1 43.19,59.7 42.31,58.82 J16.3
  BOTTOM w0.114: R126.2 55.19,55.48 54.62,55.48 D29.1 54.23,55.45 54.11,55.57 53.75,55.57 53.35,55.96 53.35,57.98 53.02,58.31 44.09,58.31 43.14,59.25 43.14,60.15 v1(42.97,60.32)
USB3_HOST1_SSRXN: length 14
  TOP w0.114: R127.1 52.12,56.41 52.12,56.86 52.32,57.06 52.32,57.4 v1(52.54,57.62) ; M1.14 58.65,51.94 58.65,53.32 58.4,53.57 58.02,53.57 v1(57.8,53.8)
  BOTTOM w0.114: v1(57.8,53.8) 57.58,53.58 53.19,53.58 52.32,54.44 52.32,57.4 v1(52.54,57.62)
USB3_HOST1_SSRXP: length 14.1
  TOP w0.114: v1(57.8,53.12) 58.01,53.33 58.3,53.33 58.41,53.22 58.41,51.94 M1.15 ; R128.1 51.88,56.52 51.88,56.96 52.08,57.16 52.08,57.4 v1(51.86,57.62)
  BOTTOM w0.114: v1(51.86,57.62) 52.08,57.4 52.08,54.34 53.09,53.34 57.58,53.34 v1(57.8,53.12)
USB3_HOST1_SSTXN: length 18.6
  TOP w0.114: v1(59.94,53.59) 60.2,53.34 60.4,53.34 60.65,53.08 60.65,51.94 M1.12 ; v1(50,57.39) 49.78,57.17 49.78,56.46 C125.1
  BOTTOM w0.114: v1(59.94,53.59) 59.69,53.34 58.84,53.34 57.44,51.94 53.17,51.94 49.78,55.33 49.78,57.18 v1(50,57.39)
USB3_HOST1_SSTXP: length 18.5
  TOP w0.114: v1(59.94,52.92) 60.13,53.1 60.3,53.1 60.41,52.98 60.41,51.94 M1.13 ; C126.1 49.54,56.46 49.54,57.17 v1(49.32,57.39)
  BOTTOM w0.114: v1(49.32,57.39) 49.54,57.16 49.54,55.23 53.07,51.7 57.54,51.7 58.94,53.1 59.76,53.1 v1(59.94,52.92)
USB3_HOST1SSRXN: length 19.4
  TOP w0.114: R127.2 52.09,54.81 52.09,53.99 50.56,52.46 44.22,52.46 42.69,54 42.69,54.57 42.56,54.7 D30.1 D30.10 42.56,56.28 42.69,56.41 42.69,56.54 42.58,56.65 41.92,56.65 41.67,56.4 40.4,56.4 40.14,56.66 40.14,57.01 39.31,57.85 J16.5
USB3_HOST1SSRXP: length 19.5
  TOP w0.114: J16.6 41.31,57.87 40.39,56.95 40.39,56.76 40.5,56.64 41.57,56.64 41.83,56.91 42.67,56.91 42.93,56.64 42.93,56.51 43.06,56.38 D30.9 D30.2 43.06,54.7 42.93,54.57 42.93,54.1 44.32,52.7 50.46,52.7 51.23,53.48 51.23,53.64 51.11,53.77 51.11,53.95 51.27,54.11 51.41,54.11 51.56,53.96 51.72,53.96 51.85,54.09 51.85,55.09 51.76,55.18 R128.2
USB3_HOST1SSTXN: length 14.5
  TOP w0.114: J16.8 45.31,57.82 46.2,56.92 46.2,56.74 46.09,56.63 45.45,56.63 45.18,56.9 44.45,56.9 44.19,56.64 44.19,56.4 44.06,56.27 D30.7 D30.4 44.06,54.7 44.19,54.57 44.19,53.77 44.68,53.27 48.95,53.27 49.78,54.1 49.78,54.79 C125.2
USB3_HOST1SSTXP: length 14.5
  TOP w0.114: J16.9 47.31,57.77 46.44,56.91 46.44,56.64 46.19,56.39 45.35,56.39 45.09,56.65 44.55,56.65 44.43,56.54 44.43,56.41 44.56,56.28 D30.6 D30.5 44.56,54.7 44.43,54.57 44.43,53.87 44.78,53.52 48.85,53.52 48.95,53.61 48.95,53.77 48.72,54 48.72,54.13 48.91,54.32 49.05,54.32 49.27,54.1 49.43,54.1 49.54,54.2 49.54,54.79 C126.2
USB_HOST2_DM: length 89.1
  TOP w0.114: M1.101 39.03,11.98 39.41,12.36 39.41,12.83 39.94,13.36 39.94,15.38 40.4,15.84 40.4,36.98 39.53,37.86 39.53,38.99 40.84,40.31 40.84,42.05 v1(40.62,42.27) ; R325.1 91.11,32.49 90.32,32.49 89.4,33.41 89.4,33.86 v1(89.23,34.03)
  BOTTOM w0.114: v1(40.62,42.27) 40.83,42.06 40.83,41.78 41.09,41.52 45.97,41.52 46.43,41.99 48.15,41.99 49.62,40.51 55.39,40.51 56.01,39.9 65.89,39.9 66.51,40.51 73.45,40.51 76.01,37.95 84.17,37.95 87.31,34.81 89.18,34.81 89.45,34.55 89.45,34.25 v1(89.23,34.03)
USB_HOST2_DM_: length 21.8
  TOP w0.114: J39.2 102.23,36.34 102.12,36.46 100.74,36.46 100.09,37.11 100.09,40.12 99.56,40.65 96.24,40.65 94.74,39.16 94.74,32.96 94.42,32.65 94.01,32.65 D46.1 92.93,32.65 92.68,32.65 R325.2
USB_HOST2_DP: length 89.1
  TOP w0.114: v1(89.91,34.03) 89.64,33.76 89.64,33.51 90.42,32.73 91.26,32.73 91.37,32.85 R326.1 ; M1.102 40.03,12.04 39.65,12.42 39.65,12.73 40.18,13.26 40.18,15.28 40.64,15.74 40.64,37.08 39.77,37.96 39.77,38.89 41.08,40.21 41.08,42.05 v1(41.3,42.27)
  BOTTOM w0.114: v1(41.3,42.27) 41.08,42.04 41.08,41.88 41.19,41.76 45.87,41.76 46.33,42.23 48.25,42.23 49.72,40.75 55.49,40.75 56.11,40.14 65.79,40.14 66.41,40.75 73.55,40.75 76.11,38.19 84.27,38.19 87.41,35.05 89.28,35.05 89.69,34.65 89.69,34.25 v1(89.91,34.03)
USB_HOST2_DP_: length 21.8
  TOP w0.114: J39.3 102.23,36.81 102.12,36.7 100.84,36.7 100.33,37.21 100.33,40.22 99.66,40.89 96.14,40.89 94.5,39.26 94.5,33.06 94.32,32.89 94.01,32.89 D47.1 92.93,32.89 92.63,32.89 R326.2
USB_HOST3_DM: length 45.9
  TOP w0.114: v1(37.19,10.77) 37.41,10.99 37.41,11.18 M1.99 ; v1(77.44,19.81) 77.55,19.7 77.72,19.7 77.83,19.81 R299.1
  BOTTOM w0.114: v1(37.19,10.77) 37.41,10.99 37.41,11.25 37.78,11.61 39.21,11.61 45.36,17.77 45.87,17.77 46.54,18.43 72.66,18.43 73.79,19.56 77.2,19.56 v1(77.44,19.81)
USB_HOST3_DP: length 45.9
  TOP w0.114: M1.100 37.65,11.18 37.65,10.99 v1(37.87,10.77) ; v1(77.44,19.08) 77.62,19.25 77.78,19.25 R298.1
  BOTTOM w0.114: v1(77.44,19.08) 77.2,19.32 76.58,19.32 76.47,19.21 76.47,19.19 76.35,19.08 76.12,19.08 76.01,19.19 76.01,19.21 75.9,19.32 73.89,19.32 72.76,18.19 46.64,18.19 45.97,17.53 45.46,17.53 39.31,11.37 37.88,11.37 37.65,11.15 37.65,10.99 v1(37.87,10.77)
USB_OTG0_DM: length 13.9
  TOP w0.114: M1.20 53.03,51.13 52.65,50.75 52.65,50.43 v1(52.87,50.22)
  BOTTOM w0.114: R116.1 62.44,53.96 62.44,53.63 60.77,51.96 59.73,51.96 58.57,50.8 52.79,50.8 52.65,50.66 52.65,50.43 v1(52.87,50.22)
USB_OTG0_DM_2: length 6.6
  TOP w0.114: v1(62.7,58.83) 62.51,58.64 62.51,58.47 63.36,57.62 J15.2
  BOTTOM w0.114: v1(62.7,58.83) 62.45,58.58 62.45,56.42 62.61,56.26 D26.2 62.44,55.78 62.44,55.51 R116.2
USB_OTG0_DP: length 13.9
  TOP w0.114: M1.21 52.03,51.09 52.41,50.71 52.41,50.43 v1(52.19,50.22)
  BOTTOM w0.114: R118.1 62.2,53.96 62.2,53.73 60.67,52.2 59.63,52.2 58.47,51.04 52.69,51.04 52.41,50.76 52.41,50.43 v1(52.19,50.22)
USB_OTG0_DP_2: length 6.7
  TOP w0.114: v1(62.02,58.83) 62.22,58.62 62.22,58.46 61.36,57.6 J15.3
  BOTTOM w0.114: v1(62.02,58.83) 62.21,58.63 62.21,56.38 62.1,56.26 D27.1 62.2,55.78 62.2,55.51 R118.2
USB_OTG0_ID: length 21
  TOP w0.127: M1.18 55.03,53 56.01,53.98 56.01,56.01 58.17,58.17 58.17,61.47 59.35,62.65 v1(64.64,62.65)
  BOTTOM w0.127: Q5.3 67.06,62.99 66.72,62.65 v1(64.64,62.65)
USB_OTG0_VBUSDET: length 8.4
  TOP w0.127: v1(55.5,54.23) 55.49,54.23 54.03,52.77 M1.19
  BOTTOM w0.127: v1(55.5,54.23) 55.63,54.1 57.02,54.1 57.78,54.86 R123.2 R121.1 59.56,56.06 R120.2
VOLN: length 27.5
  TOP w0.381: L22.2 88.14,29.84 88.97,30.68 C193.1 89.47,30.68 89.87,30.27 v1(89.87,29.93)
  BOTTOM w0.381: v1(89.87,29.93) 90.17,29.63 93.91,29.63 95.39,31.11 98.09,31.11 99.06,30.14 99.06,18.5 98.18,17.62 97.39,17.62 J25.4
VOLP: length 30.5
  TOP w0.381: v1(90.09,30.91) 89.8,31.21 88.69,32.32 C192.1 88.08,32.13 L21.2
  BOTTOM w0.381: v1(90.09,30.91) 90.09,30.55 90.5,30.14 93.7,30.14 95.18,31.62 98.3,31.62 99.57,30.35 99.57,18.29 98.3,17.02 97.55,17.02 J25.3
VORN: length 31.2
  TOP w0.381: L24.2 88.52,26.35 88.52,26.35 88.9,26.73 88.9,27.49 C198.1 89.04,27.61 89.11,27.61 89.71,28.2 89.71,28.47 v1(89.7,28.48)
  BOTTOM w0.381: v1(89.7,28.48) 89.85,28.62 94.33,28.62 95.79,30.08 97.51,30.08 97.92,29.68 97.92,19.94 97.64,19.67 95.84,19.67 94.84,18.67 94.84,15.7 96.3,14.24 J25.2
VORP: length 35.8
  TOP w0.381: v1(88.27,28.96) 87.95,28.64 C197.1 87.95,27.87 88.08,27.75 L23.2
  BOTTOM w0.381: v1(88.27,28.96) 88.27,29.36 88.65,29.74 89.23,29.74 89.84,29.13 94.12,29.13 95.58,30.59 97.72,30.59 98.42,29.89 98.42,19.73 97.85,19.16 96.25,19.16 95.45,18.36 95.45,15.93 96.14,15.24 97.36,15.24 97.84,14.76 97.84,13.31 J25.1
WIFI1T1R_CLK: length 3.4
  TOP w0.127: R67.2 C76.2 80.03,41.02 U10.17
WIFI1T1R_XTAL_IN: length 6.6
  TOP w0.203: U10.10 83.01,47.73 C78.1 82.17,48.57 82.17,51.69 82.56,52.08 XT2.3
WIFI1T1R_XTAL_OUT: length 1.5
  TOP w0.203: U10.11 82.11,47.61 R68.2
WIFIBT_32KIN_1T1R: length 2.8
  TOP w0.127: U10.24 83.01,33.77 R73.2 R74.2
N17053074: length 6.6
  TOP w0.508: U10.2 90.21,47.54 arc(90.37,47.91) 90.74,48.06 C79.2 92.19,48.06 arc(93.84,47.57) C77.2
N17053234: length 3.2
  TOP w0.508: J11.2 97.16,46.23 C80.2 95.83,46.23 C77.1
N19277328: length 1.8
  BOTTOM w0.381: U22.1 8.34,32.27 7.86,32.75 C181.2
N19277330: length 1.7
  BOTTOM w0.381: C181.1 7.52,33.57 U22.3
N19277334: length 1.9
  BOTTOM w0.381: C182.2 7.85,34.22 U22.4
N19277336: length 2
  BOTTOM w0.381: C182.1 7.52,35.55 8.2,34.87 U22.5
N19277340: length 3.2
  BOTTOM w0.381: C183.2 11.36,32.07 10.52,32.92 U22.2
N19277344: length 2.2
  BOTTOM w0.381: C184.2 8.03,36.02 8.03,35.76 8.27,35.52 U22.6
N19354508: length 5.4
  BOTTOM w0.381: R63.1 83,2.2 83.38,1.82 84.52,1.82 84.91,2.2 C394.1 R64.2 85.91,3.35 85.53,3.73 U9.4
N19356461: length 2.6
  BOTTOM w0.381: U7.4 80.45,3.36 80.07,2.98 R57.2 R56.1
N19357233: length 2.5
  BOTTOM w0.381: U8.4 90.1,3.49 89.72,3.11 R60.2 R59.1
N19781253: length 2.4
  BOTTOM w0.381: C176.2 7.16,24.66 8.53,24.66 9.09,25.22 U21.1
N19781255: length 2.8
  BOTTOM w0.381: C176.1 7.66,25.44 7.85,25.63 7.85,26.11 8.32,26.58 U21.3
N19781259: length 2.3
  BOTTOM w0.381: U21.4 8.13,27.23 7.47,26.58 C177.2
N19781261: length 2.2
  BOTTOM w0.381: C177.1 7.66,27.48 7.96,27.78 8.98,27.78 U21.5
N19781265: length 2.4
  BOTTOM w0.127: U21.2 9.75,25.93 10.08,25.6 C178.2
N19781269: length 1.5
  BOTTOM w0.381: U21.6 7.75,28.53 C179.2
N19781407: length 1.8
  BOTTOM w0.127: U21.9 15.94,29.83 R177.2
N20037713: length 1.6
  BOTTOM w0.127: R178.2 16.44,27.88 U21.12
N20144283: length 10.7
  BOTTOM w0.127: R189.2 13.34,41.27 16.99,37.62 16.99,35.52 16.34,34.87 U22.12
N20144293: length 4.2
  BOTTOM w0.127: R190.2 12.83,39.13 12.83,38.35 14.36,36.82 U22.9
N67159131: length 1.1
  BOTTOM w0.381: R136.1 91.01,16.01 U15.3
N68563646: length 3.8
  BOTTOM w0.127: U5.1 66.54,30.62 66.77,30.85 C30.2 66.33,31.82 66.33,32.07 65.86,32.54 XT1.2
N68563661: length 3.8
  BOTTOM w0.127: U5.2 67.19,30.67 C31.2 68.36,31.83 XT1.1
N68693421: length 1.4
  BOTTOM w0.381: R148.1 92.43,30.8 U17.3
N68696061: length 1.3
  BOTTOM w0.381: U18.3 91.14,20.7 R153.1
N68696295: length 1.4
  BOTTOM w0.381: U19.3 91.01,11.86 91.5,11.37 R158.1
N69227462: length 5.4
  TOP w0.254: C397.2 16.89,34.99 R5.2 17.1,34.36 17.59,33.87 17.6,33.87 R7.2 18.01,32.55 17.4,31.94 17.4,31.5 17.61,31.29 U1.5
N69227513: length 3.3
  TOP w0.254: U1.6 18.32,31.79 18.92,32.38 R8.2 C6.1 R3.1
N69227918: length 2.7
  TOP w0.381: U3.5 13.78,24.97 12.77,24.97 R12.2 R10.1
N69724413: length 1.6
  TOP w0.381: U3.1 13.67,22.78 13.46,22.99 R11.2
N69863572: length 2.4
  TOP w0.203: R68.1 C81.2 80.64,50.08 XT2.1
N69911722: length 3.2
  BOTTOM w0.381: R48.2 41.85,7.05 41.32,6.52 U6.3
N69911786: length 4.9
  TOP w0.305: 46.35,5.49 46.58,5.71 J8.17
  TOP w0.508: v1(44.32,5.49) 46.35,5.49
  BOTTOM w0.508: C53.2 R38.2 v1(44.32,5.49)
N69966336: length 5.9
  TOP w0.381: R1210.2 16.69,55.09 17.38,55.79 J12.12
N69966774: length 11.2
  TOP w0.381: v1(19.18,30.23) 20.01,31.06 C2.1
  L3_S2 w0.381: v1(19.18,30.23) 19.18,32.64 18.03,33.78 15.62,33.78 13.82,31.98 v1(13.11,31.98)
N69967080: length 1.4
  TOP w0.254: U1.4 18.52,30.79 C2.2
N70130938: length 3.7
  BOTTOM w0.127: C388.2 32.13,26.58 32.59,26.12 32.91,26.12 33.22,25.81 34,25.81 34.54,25.27 U11.29
N70266506: length 56.3
  TOP w0.381: v1(37.51,47.16) 37.51,47.01 37.41,46.92 37.41,44.5 39.52,42.39 39.52,40.8 37.95,39.22 37.95,36.89 34.16,33.1 34.16,29.21 38.79,24.58 38.79,19.76 39.2,19.35 39.2,18.55 38.62,17.97 32.74,17.97 v1(32.42,17.65) ; J12.9 31.38,56.04 33.2,54.23 34.82,54.23 v1(34.85,54.2)
  BOTTOM w0.381: v1(37.51,47.16) 37.38,47.16 36.52,48.02 35.32,48.02 34.85,48.49 v1(34.85,54.2) ; v1(32.42,17.65) 32.35,17.58 R1211.2
N70266836: length 3
  BOTTOM w0.203: 31.09,21.44 31.51,21.86 U11.19
  BOTTOM w0.381: R1203.1 29.97,20.32 31.09,21.44
N70527306: length 6.7
  TOP w0.127: J22.1 10.9,46.33 11.05,46.48 11.05,49.66 10.54,50.16 D35.2 10.57,50.57 11.5,51.5 R161.2
N70527342: length 9.4
  TOP w0.127: R162.2 10.1,38.28 9.17,39.22 D36.2 9.14,39.56 9.27,39.69 9.27,42.29 8.26,43.31 8.26,44.7 8.64,45.09 J22.2
N70531034: length 9.1
  BOTTOM w0.381: R34.1 84.71,52.58 84.45,52.32 83.69,52.32 83.31,52.7 83.31,53.59 83.57,53.85 R32.1 83.3,54.79 81.66,54.79 80.9,55.55 D12.C
N70572735: length 2.4
  TOP w0.635: 8.33,12.19 J31.9 ; J31.9 9.14,11.38 ; J31.9 9.96,12.19
N70591036: length 1
  TOP w0.254: 18.12,41.83 U2.5
  TOP w0.381: 18.12,41.83 18.52,41.83 R6.2
N70591050: length 5.2
  TOP w0.381: C3.1 19.5,40.59 19.12,40.21 v1(18.24,40.21)
  BOTTOM w0.381: v1(15.38,41.4) 17.17,41.4 18.24,40.34 v1(18.24,40.21)
N70591060: length 3.7
  TOP w0.254: 17.59,42.74 U2.6
  TOP w0.381: C13.1 R4.1 18.54,43.87 R9.2 17.53,42.8 17.59,42.74
N70591176: length 1.2
  TOP w0.305: C3.2 18.17,41.33 U2.4
N70593664: length 11.5
  TOP w0.305: J9.1 64.88,6.15 65.06,5.96 65.41,5.96 65.66,6.21
  TOP w0.381: v1(67.69,6.22) 67.68,6.21 65.66,6.21
  BOTTOM w0.381: v1(67.69,6.22) 69.22,6.22 70.23,7.24 70.23,9.14 70.68,9.59 C61.1 71.25,9.77 R47.2 R46.2
N70626310: length 5.3
  TOP w0.127: M1.57 23.09,42.06 20.12,45.03 R16.2
N70633183: length 1.5
  BOTTOM w0.381: R129.2 54.35,63.05 U14.3
N70633229: length 1.3
  TOP w0.381: R122.2 71.88,55.24 72.07,55.44 U13.3
N70633628: length 2.7
  BOTTOM w0.127: R117.1 R119.1 67.69,60.96 67.56,61.1 Q5.1
N70648039: length 8.7
  TOP w0.203: J34.5 99.92,58.48 v1(99.9,58.5)
  BOTTOM w0.203: R166.2 R164.1 100.3,61.53 D38.1 100.33,61.5 C159.2 101.42,60.02 v1(99.9,58.5)
N70649018: length 2
  BOTTOM w0.203: R170.1 C161.2 R169.2
N70649944: length 2.4
  TOP w0.203: R167.2 91.67,50.07 91.71,50.07 C158.2 R163.2
N70663154: length 1.6
  TOP w0.381: R14.1 18.14,16.31 17.84,16.61 U4.4
N70663167: length 1.6
  TOP w0.381: R1220.2 18.23,15.06 17.84,14.67 U4.3
N70672743: length 1.3
  TOP w0.203: U24.2 80.45,30.42 C186.2
N70672808: length 1.9
  TOP w0.203: C187.2 78.85,29.59 79.1,29.59 79.31,29.39 R197.1
N70672810: length 1.4
  TOP w0.203: U24.3 80.8,29.77 R197.2
N70672945: length 1.9
  TOP w0.203: R198.1 78.74,28.76 78.74,29.08 78.42,29.41 C188.2
N70672947: length 1.6
  TOP w0.203: R198.2 81.14,29.12 U24.4
N70673300: length 1.2
  TOP w0.381: U24.8 86.07,31.07 86.11,31.11 L21.1
N70673587: length 1.5
  TOP w0.381: U24.5 85.99,29.12 86.68,29.81 L22.1
N70674127: length 1.2
  TOP w0.203: C194.2 80.26,27.12 U25.2
N70674131: length 1.3
  TOP w0.203: C195.2 78.24,26.29 R200.1
N70674133: length 1.3
  TOP w0.203: R200.2 80.39,26.47 U25.3
N70674155: length 1.3
  TOP w0.203: C196.2 78.3,25.27 R201.1
N70674157: length 1.4
  TOP w0.203: U25.4 80.76,25.82 R201.2
N70674204: length 1.4
  TOP w0.381: L23.1 86.08,27.77 U25.8
N70674215: length 1.2
  TOP w0.381: L24.1 86.11,25.91 86.02,25.82 U25.5
N70676752: length 3.1
  TOP w0.305: R295.2 81.24,16.31 U26.8
N70676766: length 1.5
  TOP w0.305: R301.1 83.11,21.59 83.31,21.39 U26.25
N70676768: length 1.5
  TOP w0.305: U26.24 83.81,21.64 84,21.83 R300.1
N70676770: length 1.7
  TOP w0.305: R293.1 84.89,22.07 84.31,21.5 U26.23
N70676772: length 2.1
  TOP w0.305: R294.1 85.78,21.83 85.49,21.55 85.07,21.55 84.81,21.29 U26.22
N70676774: length 1.6
  TOP w0.305: U26.19 87.25,18.79 R292.1
N70676824: length 1.8
  TOP w0.305: U26.20 86.52,19.29 87.17,19.94 R302.1
N70676921: length 1.8
  TOP w0.381: R296.2 80.05,17.65 80.19,17.79 U26.5
N70676923: length 4.2
  TOP w0.305: U26.9 82.31,15.11 81.83,14.63 R297.2
N70708323: length 1.8
  BOTTOM w0.381: U27.3 91.14,26.01 92.1,25.04 R327.1
N70802303: length 1.9
  BOTTOM w0.381: C371.2 22.8,38.16 22.61,38.35 U23.7
N70802422: length 1.9
  BOTTOM w0.381: U23.2 28.96,38.73 28.63,38.41 C372.2
N70802644: length 7
  BOTTOM w0.381: R1229.1 19.3,47.88 20.45,46.74 22.23,46.74 22.61,47.12 U23.10
N70803761: length 6.3
  BOTTOM w0.381: U23.15 28.96,46.99 29.23,46.72 30.34,46.72 30.99,47.37 R1228.1
N70846219: length 2.2
  BOTTOM w0.203: R1207.1 37.48,25.15 U11.1
N70854426: length 19.9
  BOTTOM w0.127: U9.3 85.28,5.63 85.47,5.44 ; 85.47,5.44 85.95,5.44 86.18,5.21 87.2,5.21 87.58,4.83 89.98,4.83 90.1,4.95 U8.3 ; 85.47,5.44 85.28,5.24 85.28,4.65 85.15,4.52 83.74,4.52 83.15,5.12 80.8,5.12 80.45,5.46 ; 80.45,5.46 80.11,5.12 77.1,5.12 76.45,5.77 R1221.2 ; 80.45,5.46 U7.3
N70857622: length 10.4
  TOP w0.127: v1(67.31,64.54) 68.81,66.04 71.81,66.04 73.23,67.46 LED3.1
  BOTTOM w0.127: v1(67.31,64.54) 67.89,64.54 68.71,63.72 R19.2
N70857637: length 2.5
  TOP w0.127: v1(70.23,66.8) 70.03,67 LED3.2
  BOTTOM w0.127: v1(70.23,66.8) 70.61,66.42 Q10.3
N70857653: length 1.6
  BOTTOM w0.127: R1227.2 71.11,63.43 Q10.1
N70869941: length 1.8
  BOTTOM w0.381: C396.2 R1228.2
N70869956: length 1.9
  BOTTOM w0.381: R1229.2 C395.2
N70885563: length 4.2
  TOP w0.305: R1230.2 89.59,9.59 89.28,9.29 89.28,8.13 89.77,7.64 90.24,7.64 90.55,7.34 J7.4
N70966122: length 2.8
  BOTTOM w0.203: R232.1 77.81,54.12 R231.2 77.81,53.31 U28.3
N70966143: length 3.8
  BOTTOM w0.127: U28.2 78.93,48.94 D86.A 80.12,48.51 R1231.1
N76750177: length 2
  BOTTOM w0.203: U11.2 37.06,23.86 37.34,24.13 37.36,24.13
  BOTTOM w0.381: C385.2 37.36,24.13

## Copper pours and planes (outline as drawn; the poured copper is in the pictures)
GND on L2_GND: 1.27,0.38 0.64,0.64 0.38,1.27 0.38,68.71 0.64,69.34 1.27,69.6 13.97,69.6 14.22,69.34 14.22,56.36 17.45,53.14 31.83,53.14 34.72,56.03 34.72,67.92 34.68,67.96 34.68,69.35 34.92,69.6 95.89,69.6 95.89,68.33 100.2,68.33 100.2,69.6 103.76,69.6 104.39,69.34 104.65,68.71 104.65,1.27 104.39,0.64 103.76,0.38 ; 1 cut-out
GND on L3_S2: 14.66,67.16 14.58,67.23 0.41,67.23 0.38,67.26 0.38,68.71 0.64,69.34 1.27,69.6 16.92,69.6 17.17,69.34 17.17,68 14.99,68 14.3,67.31 14.53,67.31 14.94,67.72 17.17,67.72 17.17,62.84 16.41,62.08 16.41,60.45 16.79,60.07 31.98,60.07 31.98,50.57 33.6,48.95 33.68,48.95 33.76,48.87 34.57,48.87 34.57,68.2 34.06,68.71 31.88,68.71 31.85,68.73 31.85,69.34 32.11,69.6 95.89,69.6 95.89,68.33 100.2,68.33 100.2,69.6 103.76,69.6 104.39,69.34 104.65,68.71 104.65,1.27 104.39,0.64 103.76,0.38 1.27,0.38 0.64,0.64 0.38,1.27 0.38,51.18 1.75,51.18 1.88,51.31 1.6,51.59 0.38,51.59 0.38,67.01 14.5,67.01 ; 8 cut-outs
GND on L3_S2: 76.83,12.19 67.69,12.19 67.56,12.06 67.56,10.54 68.45,9.65 68.45,7.87 68.83,7.49 76.07,7.49 76.96,6.6 81.92,6.6 82.17,6.86 82.17,8.76 78.11,12.83 77.47,12.83
GND_EARTH on BOTTOM (solid shape): 8.2,56.29 8.2,53.67 6.4,51.87 3.73,51.87 1.93,53.67 1.93,56.26 3.71,58.04 6.45,58.04
GND_EARTH on L3_S2 (solid shape): 6.99,57.91 8.38,56.52 8.38,53.09 7.24,51.94 3.43,51.94 1.65,53.72 1.65,56.77 2.92,58.04 6.99,58.04
GND_EARTH on TOP: 15.29,58.78 14.91,59.16 14.91,69.19 15.13,69.41 17.08,69.41 17.17,69.32 17.17,62.84 16.41,62.08 16.41,58.9 16.28,58.78
GND_EARTH on TOP: 33.27,59.56 32.37,60.46 32.41,60.5 32.41,62.2 31.62,62.99 31.62,69.47 31.75,69.6 34.04,69.6 34.16,69.47 34.16,59.82 33.91,59.56
GND_EARTH on BOTTOM: 16.48,56.46 14.91,58.04 14.91,63.09 9.4,63.09 9.4,63.12 9.02,63.5 9.02,65.41 8.76,65.66 3.17,65.66 3,65.48 2.96,65.48 1.4,63.91 1.4,58.93 2.16,58.17 6.6,58.17 8.56,56.21 8.56,51.71 8.38,51.54 0.38,51.54 0.38,67.06 0.46,67.13 4.55,67.13 5.84,66.18 7.14,67.13 14.91,67.13 14.91,67.59 15.16,67.84 16.97,67.84 17.04,67.77 17.04,62.87 16.36,62.18 16.36,60.38 16.71,60.02 31.98,60.02 32.44,60.48 32.44,62.08 31.88,62.64 31.88,63.28 31.94,63.37 32.61,63.28 32.91,63.76 32.91,65.56 32.61,66.04 31.94,65.95 31.88,66.04 31.88,67.67 31.98,67.77 33.86,67.77 33.93,67.69 33.93,55.63 32.91,54.6 32.91,48.76 29.03,44.88 19.76,44.88 19,45.64 19,47.55 19.02,47.57 19.02,49.61 18.95,49.68 18.95,51.18 19,51.23 19,51.97 18.97,51.99 18.44,51.99 18.44,56.31 18.29,56.46 ; 2 cut-outs
GND_EARTH on L2_GND: 16.97,67.84 15.16,67.84 14.91,67.59 14.91,56.59 17.78,53.72 31.24,53.72 33.93,56.41 33.93,67.69 33.86,67.77 31.98,67.77 31.88,67.67 31.88,62.64 32.44,62.08 32.44,60.48 31.98,60.02 16.71,60.02 16.36,60.38 16.36,62.18 17.04,62.87 17.04,67.77
GND_EARTH on L3_S2: 2.13,53.62 3.68,52.07 6.3,52.07 8,53.77 8,56.21 6.3,57.91 3.86,57.91 2.13,56.18
GND_EARTH on L3_S2: 7.24,51.82 3.56,51.82 3.39,51.65 0.67,51.65 0.64,51.69 0.38,51.69 0.38,66.73 0.53,66.88 14.4,66.88 15.11,67.59 17.17,67.59 17.17,62.84 16.41,62.08 16.41,60.45 16.79,60.07 31.98,60.07 32.41,60.5 32.41,61.93 31.85,62.48 31.85,67.77 33.96,67.77 33.96,49.48 31.62,49.48 30.65,48.5 21.54,48.5 21.27,48.77 21.27,51.52 17.81,54.99 10.41,54.99
